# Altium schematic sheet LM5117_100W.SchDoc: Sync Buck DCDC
size 431 x 279 mm; Engineer: Yutao Wang (Steven); Organization: TESLA Motors, INC; Address1: 3500 Deer Creek Road; Address2: Palo Alto, CA; Address4: U.S.A.; SheetNumber: 7; SheetTotal: 7
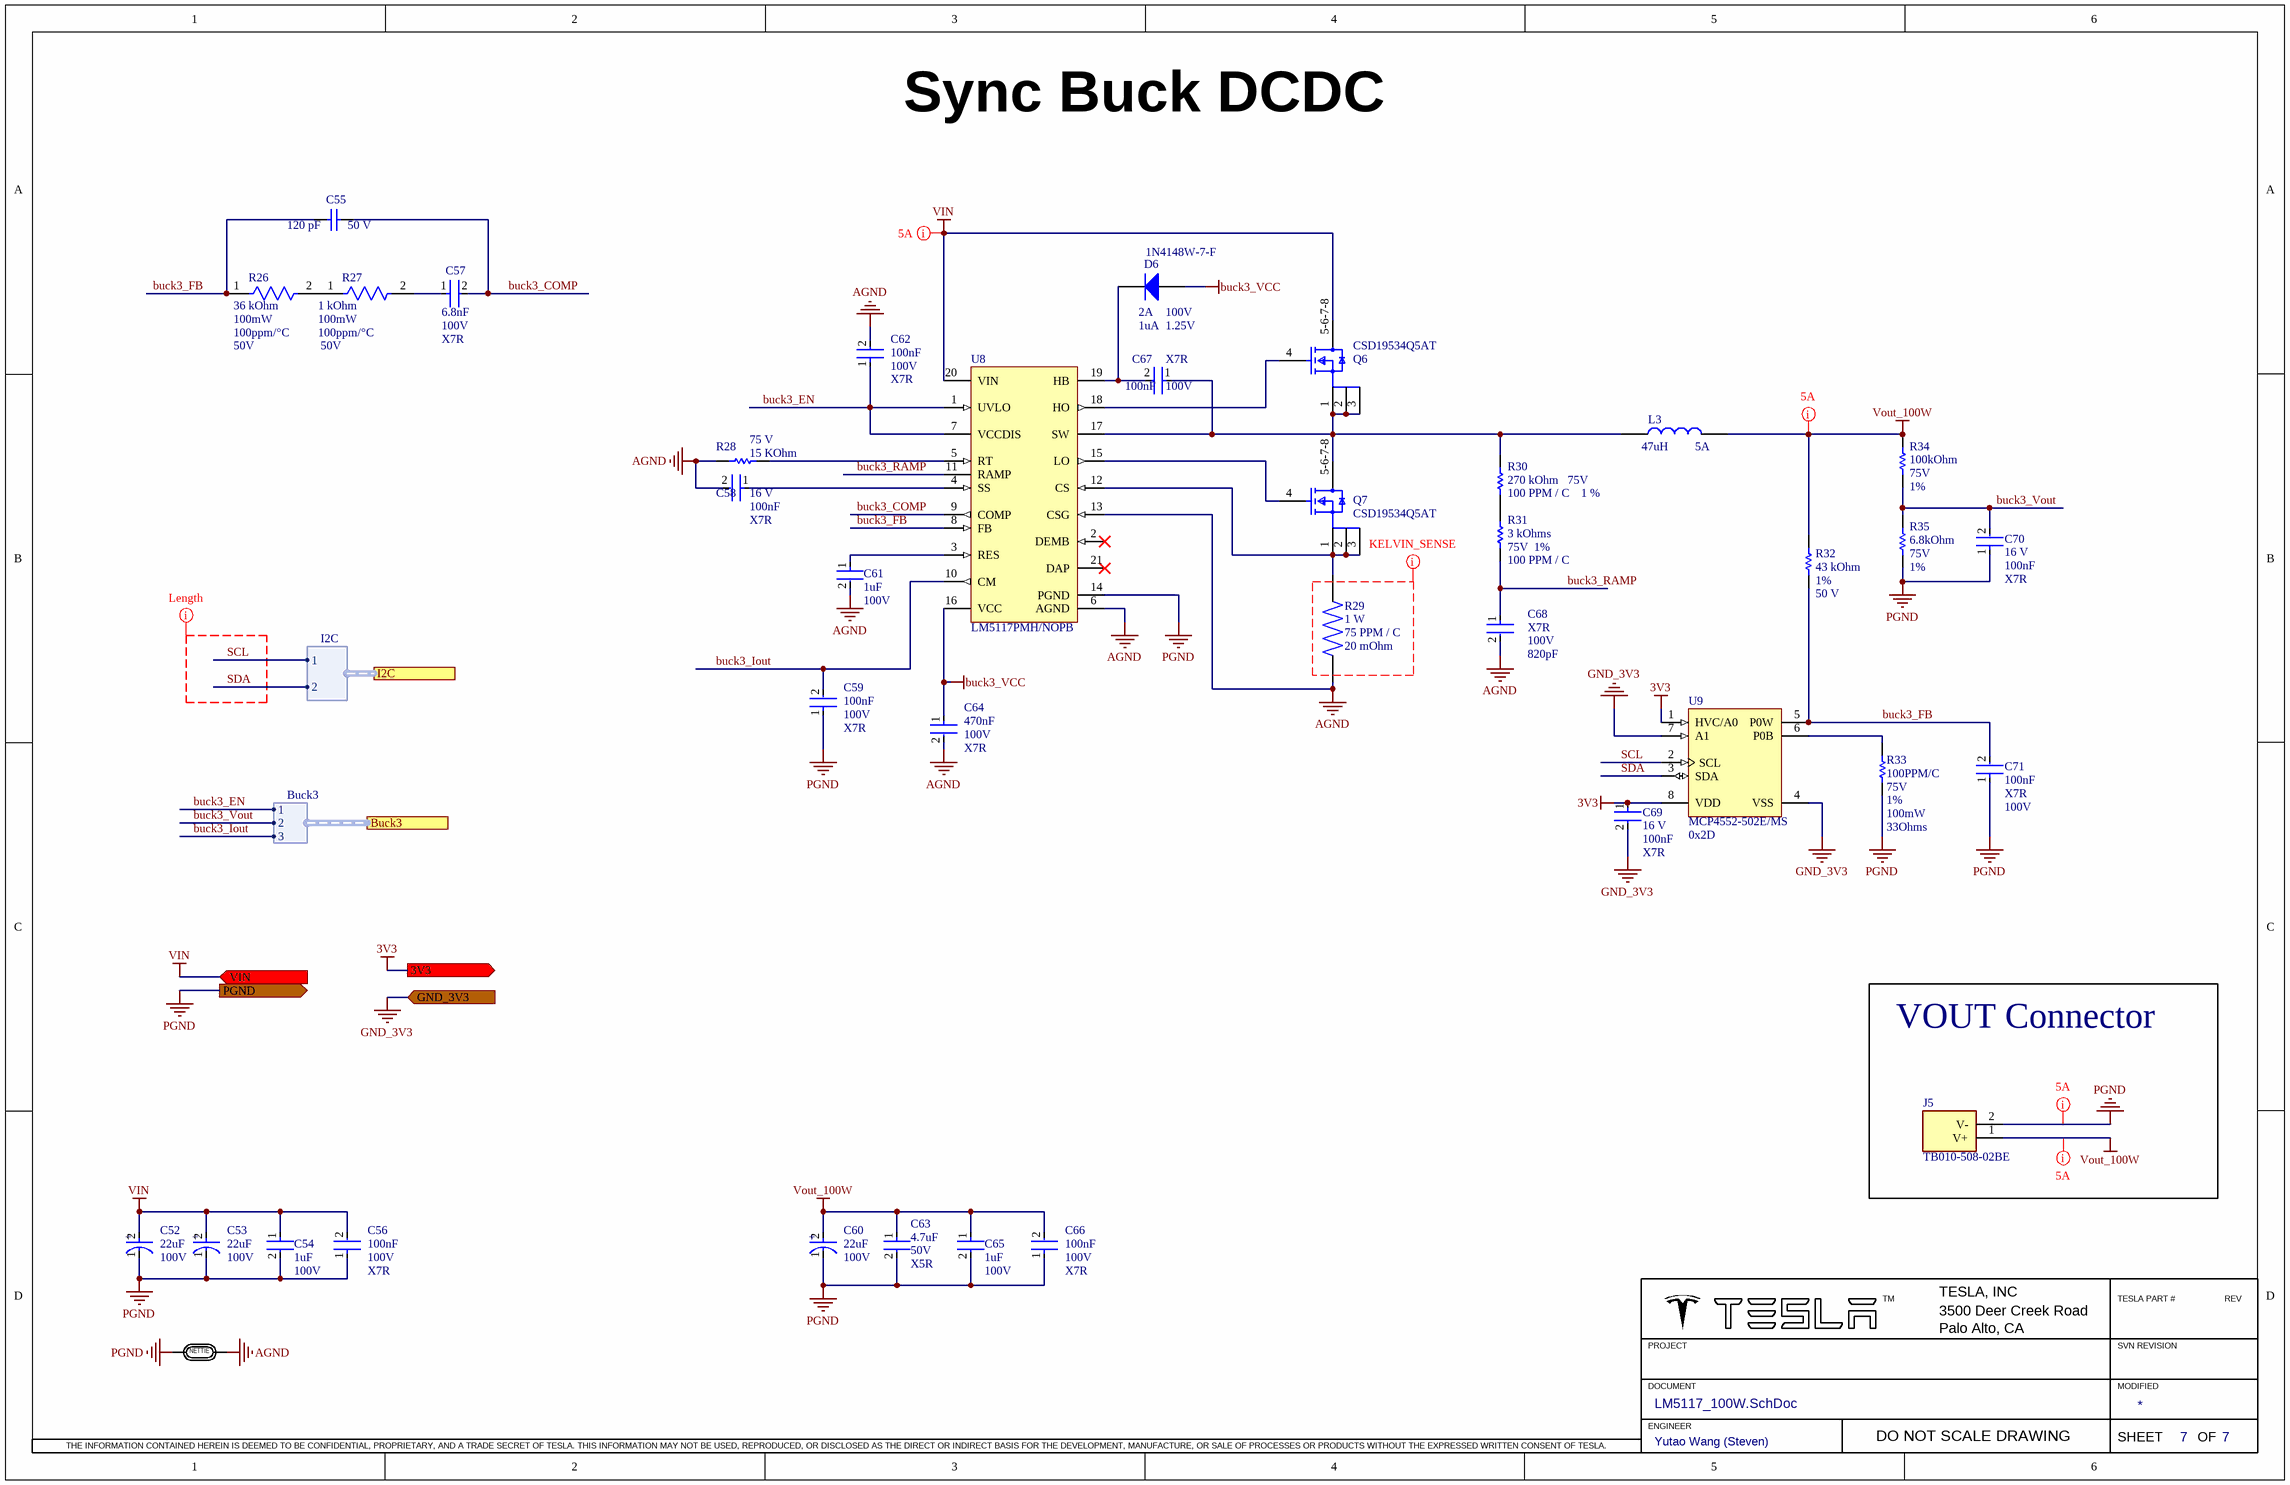
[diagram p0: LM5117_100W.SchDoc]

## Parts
C52  Capacitance: 22uF  Voltage Rating (DC): 100V  [FP-TGF-MFG]  (hidden comment: EEE-TG2A220UP)
C53  Capacitance: 22uF  Voltage Rating (DC): 100V  [FP-TGF-MFG]  (hidden comment: EEE-TG2A220UP)
C54  Capacitance: 1uF  Voltage: 100V  [FP-C2012-125-0_2-IPC_A]  (hidden comment: C2012X7S2A105K125AB)
C55  Capacitance: 120 pF  Voltage: 50 V  [CAPC1608X87X35LL15T15]  (hidden comment: C0603C121J5GACTU)
C56  Capacitance: 100nF  Dielectric: X7R  Voltage Rating (DC): 100V  [FP-CC1206-0_3-1_45-IPC_C]  (hidden comment: CC1206KKX7R0BB104)
C57  Voltage Rating: 100V  Capacitance: 6.8nF  Dielectric: X7R  [FP-GCM188-0_1-IPC_C]  (hidden comment: GCM188R72A682KA37D)
C58  Voltage Rating: 16 V  Capacitance: 100nF  Temperature Characteristic: X7R  [FP-C0402-BB-MFG]  (hidden comment: C0402C104K4RACTU)
C59  Capacitance: 100nF  Dielectric: X7R  Voltage Rating (DC): 100V  [FP-CC1206-0_3-1_45-IPC_C]  (hidden comment: CC1206KKX7R0BB104)
C60  Capacitance: 22uF  Voltage Rating (DC): 100V  [FP-TGF-MFG]  (hidden comment: EEE-TG2A220UP)
C61  Capacitance: 1uF  Voltage: 100V  [FP-C2012-125-0_2-IPC_A]  (hidden comment: C2012X7S2A105K125AB)
C62  Capacitance: 100nF  Dielectric: X7R  Voltage Rating (DC): 100V  [FP-CC1206-0_3-1_45-IPC_C]  (hidden comment: CC1206KKX7R0BB104)
C63  Voltage Rating (DC): 50V  Capacitance: 4.7uF  Dielectric: X5R  [FP-GRM21B-0_15-IPC_C]  (hidden comment: GRM21BR61H475ME51L)
C64  Capacitance: 470nF  Voltage Rating (DC): 100V  Dielectric: X7R  [FP-GRM21B-0_15-IPC_A]  (hidden comment: GRM21BR72A474MA73L)
C65  Capacitance: 1uF  Voltage: 100V  [FP-C2012-125-0_2-IPC_A]  (hidden comment: C2012X7S2A105K125AB)
C66  Capacitance: 100nF  Dielectric: X7R  Voltage Rating (DC): 100V  [FP-CC1206-0_3-1_45-IPC_C]  (hidden comment: CC1206KKX7R0BB104)
C67  Capacitance: 100nF  Dielectric: X7R  Voltage Rating (DC): 100V  [FP-CC1206-0_3-1_45-IPC_C]  (hidden comment: CC1206KKX7R0BB104)
C68  Capacitance: 820pF  Voltage: 100V  Grade: X7R  [FP-GCM155-0_05-IPC_A]  (hidden comment: GCM155R72A821KA37J)
C69  Voltage Rating: 16 V  Capacitance: 100nF  Temperature Characteristic: X7R  [FP-C0402-BB-MFG]  (hidden comment: C0402C104K4RACTU)
C70  Voltage Rating: 16 V  Capacitance: 100nF  Temperature Characteristic: X7R  [FP-C0402-BB-MFG]  (hidden comment: C0402C104K4RACTU)
C71  Capacitance: 100nF  Dielectric: X7R  Voltage Rating (DC): 100V  [FP-CC1206-0_3-1_45-IPC_C]  (hidden comment: CC1206KKX7R0BB104)
D6  1N4148W-7-F  Max Surge Current: 2A  Peak Reverse Voltage: 100V  Ir - Reverse Current: 1uA  Vf - Forward Voltage: 1.25V  [DIOD-SOD123-2_V]
J5  TB010-508-02BE  [CUI_TB010-508-02BE]
L3  Max DC current: 5A  Inductance: 47uH  [IHLP6767DZER470M11]  (hidden comment: IHLP6767DZER470M11)
NT5  BOARD FEATURE  [NETTIE-0.5X0.5X0.4]  (value not drawn)  (net tie, no BOM)
Q6  CSD19534Q5AT  [FP-DQJ0008A-MFG]
Q7  CSD19534Q5AT  [FP-DQJ0008A-MFG]
R26  Power Rating: 100mW  Temperature Coefficient: 100ppm/°C  Voltage Rating (DC): 50V  Resistance: 36 kOhm  [FP-RC0603-0_55-IPC_C]  (hidden comment: RC0603FR-0736KL)
R27  Resistance: 1 kOhm  Voltage Rating: 50V  Power Rating: 100mW  Temperature Coefficient: 100ppm/°C  [FP-RC0603-0_55-IPC_C]  (hidden comment: RC0603FR-071KL)
R28  Resistance: 15 KOhm  Voltage: 75 V  [RESC1608X55X25LL10T15]  (hidden comment: RC0603FR-0715KL)
R29  Power: 1 W  PPM: 75 PPM / C  Resistance: 20 mOhm  [PE1206FRM470R02L]  (hidden comment: PE1206FRM470R02L)
R30  value 270 kOhm  Tolerance: 1 %  PPM: 100 PPM / C  Voltage: 75V  [RESC0603(1608)_N]  (hidden comment: RC0603FR-07270KL)
R31  Resistance: 3 kOhms  Tolerence: 1%  PPM: 100 PPM / C  Voltage: 75V  [RESC1608X55X25NL10T15]  (hidden comment: RC0603FR-073KL)
R32  Resistance: 43 kOhm  Tolerence: 1%  Voltage: 50 V  [RESC1005X40X25NL05T10]  (hidden comment: RC0402FR-0743KL)
R33  Temperature Coefficient: 100PPM/C  Voltage Rating: 75V  Tolerance: 1%  Power Rating: 100mW  Resistance: 33Ohms  [RESC1608X55X25LL10T15]  (hidden comment: RC0603FR-0733RL)
R34  Resistance: 100kOhm  Voltage: 75V  Tolerence: 1%  [RESC1608X55X30ML15T15]  (hidden comment: ERJ-3EKF1003V)
R35  Voltage: 75V  Resistance: 6.8kOhm  Tolerence: 1%  [RESC1609X55X30NL15T15]  (hidden comment: ERJ-3EKF6801V)
U8  LM5117PMH/NOPB  [PWP0020A_N]
U9  MCP4552-502E/MS  [MSOP-MS8_N]

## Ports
3V3 (out), Buck3 (harness Buck3), GND_3V3 (in), I2C (harness I2C), PGND (out), VIN (in)

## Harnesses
Buck3: 1, 3, 2
I2C: 1, 2

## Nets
3V3: C69.1 U9.1(HVC/A0) U9.8(VDD) ; port 3V3
AGND: C58.2 C61.2 C62.2 C64.2 C68.2 NT5.1(C1) R28.1 R29.1 U8.6(AGND) U8.13(CSG)
buck3_VCC: C64.1 D6.1(A) U8.16(VCC)
GND_3V3: C69.2 U9.4(VSS) U9.7(A1) ; port GND_3V3
PGND: C52.1(C) C53.1(C) C54.2 C56.1 C59.1 C60.1(C) C63.2 C65.2 C66.1 C70.1 C71.1 J5.2(V-) NT5.2(C2) R33.2 R35.1 U8.14(PGND) ; port PGND
VIN: C52.2(A) C53.2(A) C54.1 C56.2 Q6.5-6-7-8(D) U8.20(VIN) ; port VIN
Vout_100W: C60.2(A) C63.1 C65.1 C66.2 J5.1(V+) L3.2 R32.2 R34.2
buck3_COMP: C55.2 C57.2 U8.9(COMP)
buck3_EN: C62.1 U8.1(UVLO) U8.7(VCCDIS) ; port Buck3.1
buck3_FB: C55.1 C71.2 R26.1 R32.1 U8.8(FB) U9.5(P0W)
buck3_Iout: C59.2 U8.10(CM) ; port Buck3.3
buck3_RAMP: C68.1 R31.1 U8.11(RAMP)
buck3_Vout: C70.2 R34.1 R35.2 ; port Buck3.2
SCL: U9.2(SCL) ; port I2C.1
SDA: U9.3(SDA) ; port I2C.2
NetC57_1: C57.1 R27.2
NetC58_1: C58.1 U8.4(SS)
NetC61_1: C61.1 U8.3(RES)
NetC67_1: C67.1 L3.1 Q6.1(S) Q6.2(S) Q6.3(S) Q7.5-6-7-8(D) R30.2 U8.17(SW)
NetC67_2: C67.2 D6.2(K) U8.19(HB)
NetQ6_4: Q6.4(G) U8.18(HO)
NetQ7_1: Q7.1(S) Q7.2(S) Q7.3(S) R29.2 U8.12(CS)
NetQ7_4: Q7.4(G) U8.15(LO)
NetR26_2: R26.2 R27.1
NetR28_2: R28.2 U8.5(RT)
NetR30_1: R30.1 R31.2
NetR33_1: R33.1 U9.6(P0B)

Not connected (* = marked no-connect by the designer): U8 2(DEMB)* 21(DAP)*

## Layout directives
mark named 5A: PGND, VIN, Vout_100W
net class Length: (no net found under the mark)
mark named KELVIN_SENSE: (no net found under the mark)

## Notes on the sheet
- (near U9) 0x2D
- VOUT Connector

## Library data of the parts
C52 C53 C60 = CMP-05427-002105-1: CAP ALUM 22UF 20% 100V SMD; Dissipation Factor: 0.1%; ESR (Equivalent Series Resistance): 1.3R; Ripple Current: 70mA; Life (Hours): 2000Hour
C54 C61 C65 = CMP-2000-05454-2: Multilayer Ceramic Capacitors 1μF ±10% 100V X7S SMD 0805
C55 = CMP-2006-03074-1: SMD/SMT 50V 120pF C0G 0603 5%; Manufacturer: Kemet
C56 C59 C62 C66 C67 C71 = CMP-03422-001499-1: CAP CER 0.1UF 100V X7R 1206; Dielectric Material: Ceramic; Tolerance: 10%
C57 = CMP-2006-02398-2: 6.8 nF 100 VDC 10% 0603 X7R
C58 C69 C70 = CMP-2008-02108-2: CAP CER 0.1UF 16V X7R 0402; Manufacturer: Kemet; Value: 0.10 μF; Tolerance: 0.1; Material: Ceramic; Temperature Coefficient: 15%
C63 = CMP-06035-037765-1: Chip Multilayer Ceramic Capacitors for General Purpose, 0805, 4.7uF, X5R, 15%, 20%, 50V
C64 = CMP-06035-021373-1: Chip Multilayer Ceramic Capacitors for General Purpose, 0805, 0.47uF, X7R, 15%, 20%, 100V
C68 = CMP-06035-060413-1: Ceramic Capacitor for Automotive 820pF ±10% 100VDC X7R 0402 Paper T/R
D6 = CMP-2000-04932-2: Fast Switching Diode, 100 V, 0.15 A, -65 to 150 degC, 2-Pin?SOD123, RoHS, Tape and Reel; Recovery Time: 4ns; Brand: DiodesIncorporated; Unit Weight: 0.000353oz; Configuration: Single; If - Forward Current: 0.15A
J5 = TB010-508-02BE: 2~24 Poles, Screw Type, Horizontal, 5.08 Pitch, 26~12 (AWG), Terminal Block Connector; MF: CUI Devices
L3 = IHLP6767DZER470M11: Fixed Inductors 47uH 20% Shielded; Manufacturer_Name: Vishay; Geometry.Height: 4mm; Saturation Current: 4.3A; Max DC resistance: 108mOhm
NT5 = CMP-01115-6: NET TIE 0.5 x 0.5 mm, 0.4mm GAP; Manufacturer PartNo: NONE - BOARD FEATURE; Manufacturer: TESLA; AEC-Q: YES; Level: 1; Selective Soldering: NO; Pressfit: NO; Layout Notes: NET TIE
Q6 Q7 = CMP-04962-000018-1: MOSFET N-CH 100V 50 8SON; Manufacturer: Texas Instruments; Reverse Recovery Time: 53ns; Turn Off Delay Time: 20ns; Gate To Source Voltage: 20V; Turn On Delay Time: 9ns; Depletion Mode: False; Threshold Vgs Max: 3.4V; Pulse Drain Current: 137A; Number Of N Channels: 1; Input Capacitace At Vds: 1290pF @ 50V; Max Junction Temp: +150°C; Power Dissipation: 3.2W; Max Forward Diode Voltage: 1V; Continuous Drain Current: 10A; Drain To Source Resistance: 12.6mΩ; Threshold Vgs Min: 2.4V; Transconductance: 47S; Gate Charge At Vgs: 17nC @ 10V; Reverse Recovery Charge: 134nC; Typ Forward Diode Voltage: 0.8V; Rthja Max: 50°C/W
R26 = CMP-03412-037824-1: RES 36K OHM 1% 1/10W 0603; Voltage Rating: 75V
R27 = CMP-1659-00009-5: RES 1K OHM 1% 1/10W 0603
R28 = CMP-1659-00032-1: Chip Resistor, 15 KOhm, +/- 1%, 0.1 W, -55 to 155 degC, 0603 (1608 Metric), RoHS, Tape and Reel
R29 = PE1206FRM470R02L: SMD 20 mOhms 1 Watts 1 % 75 ppm/C; Tolerence: 1 %
R30 = CMP-1012-00783-1: SMD 270 kOhms 100mW 0603 1%; Power: 0.1 W; Case-Metric: 1608; Case-EIA: 0603
R31 = CMP-2000-04040-1: SMD 3 kOhms 100mW 0603 1%; Manufacturer: Yageo
R32 = CMP-1011-00694-2: Thick Film Resistors - SMD 43 kOhms 62.5mW 0402 1%; Manufacturer: Yageo / Phycomp
R33 = CMP-2000-06939-1: Chip Resistor, 33 Ohm, +/- 1%, 0.1 W, -55 to 155 degC, 0603 (1608 Metric), RoHS, Tape and Reel; Unit Weight: 0.000071oz; Brand: Yageo
R34 = CMP-2000-00182-1: Thick Film Resistors - SMD 0603 100Kohms 1% AEC-Q200; Manufacturer: Panasonic
R35 = CMP-1012-00604-3: Chip Resistor, 6.8 KOhm, +/- 1%, 0.1 W, -55 to 155 degC, 0603 (1608 Metric), RoHS, Tape and Reel; Manufacturer PartNo: ERJ-3EKF6800V
U8 = CMP-0069-02227-2: Wide Input Range Synchronous Buck Controller with Analog Current Monitor, 20-pin TSSOP-EP, 73 Rail; Manufacturer: Texas Instruments; CompType: Switcher; High-Reliability: Y; PackageTopMarking: NSUZXYTT*LM5117*PMH
U9 = CMP-0188-00827-2: 8-Bit Single I2C Digital POT with Volatile Memory, 8-pin MSOP, Extended Temperature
